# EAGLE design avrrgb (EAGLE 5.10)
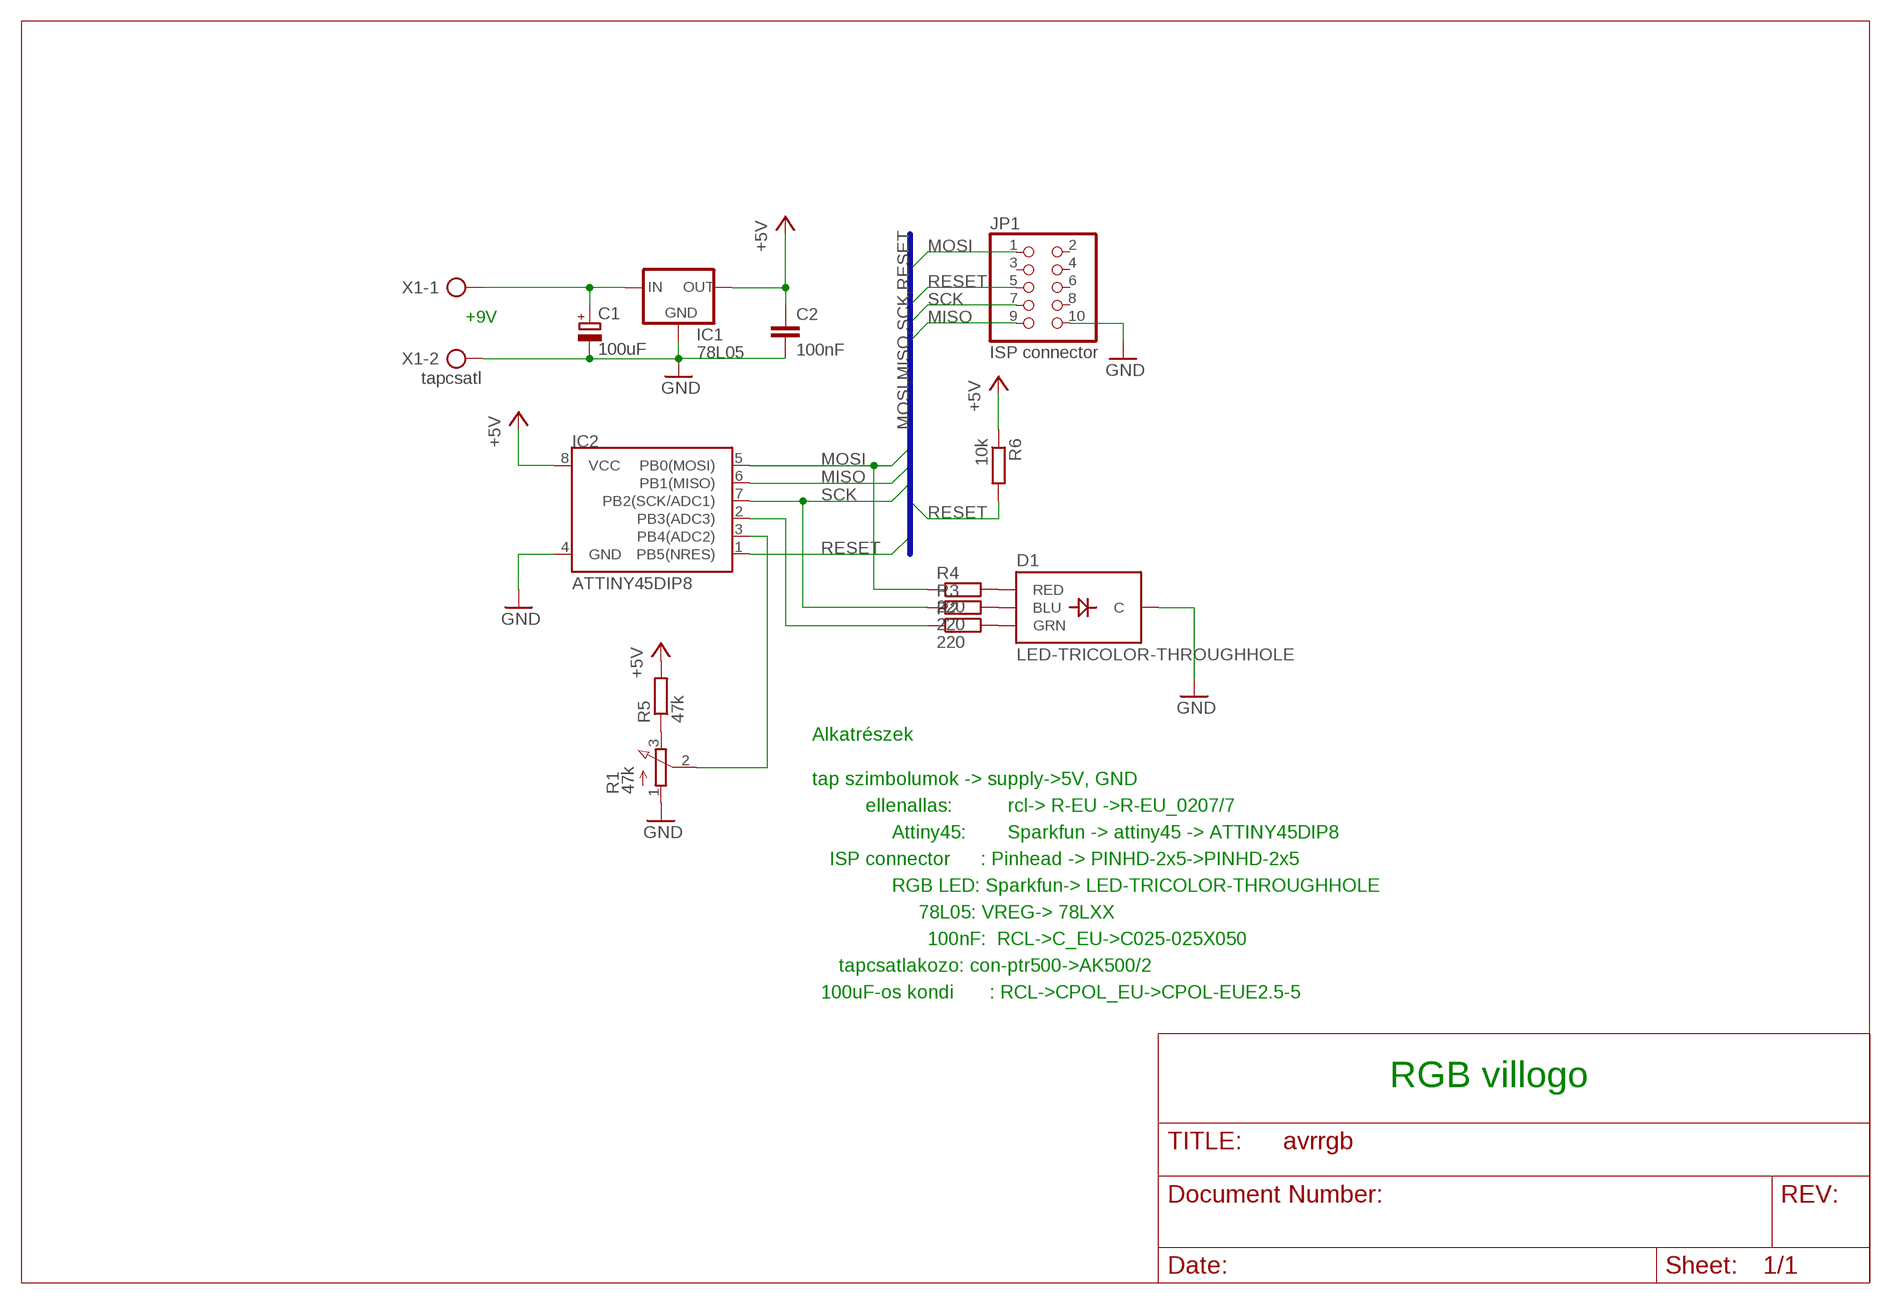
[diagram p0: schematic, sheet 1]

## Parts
C1  100uF  CPOL-EUE2.5-5  [E2,5-5]
C2  100nF  C-EU025-025X050  [C025-025X050]
D1  LED-TRICOLOR-THROUGHHOLE  [LED-TRICOLOR-THROUGHHOLE]
IC1  78L05  78LXX  [78LXX]
IC2  ATTINY45DIP8  [DIP08]
JP1  ISP connector  PINHD-2X5  [2X05]
R1  47k  3RP/1610N  [3RP/1610N]
R2  220  R-EU_0207/7  [0207/7]
R3  220  R-EU_0207/7  [0207/7]
R4  220  R-EU_0207/7  [0207/7]
R5  47k  R-EU_0207/7  [0207/7]
R6  10k  R-EU_0207/7  [0207/7]
X1  tapcsatl  AK500/2  [AK500/2]

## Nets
+5V: C2.1 IC1.OUT IC2.8(VCC) R5.2 R6.1
GND: C1.- C2.2 D1.GND(C) IC1.GND IC2.4(GND) JP1.10 R1.1(A) X1.2
MISO: IC2.6(PB1(MISO)) JP1.9
MOSI: IC2.5(PB0(MOSI)) JP1.1 R4.1
N$1: C1.+ IC1.IN X1.1
N$2: D1.GRN R2.2
N$3: D1.BLU R3.2
N$4: D1.RED R4.2
N$5: R1.3(E) R5.1
N$6: IC2.3(PB4(ADC2)) R1.2(S)
N$7: IC2.2(PB3(ADC3)) R2.1
RESET: IC2.1(PB5(NRES)) JP1.5 R6.2
SCK: IC2.7(PB2(SCK/ADC1)) JP1.7 R3.1
Unconnected: JP1.2 JP1.3 JP1.4 JP1.6 JP1.8

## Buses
MOSI,MISO,SCK,RESET

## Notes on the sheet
- +9V
- Alkatrészek
- tap szimbolumok -> supply->5V, GND
- ellenallas: | rcl-> R-EU ->R-EU_0207/7
- Attiny45: | Sparkfun -> attiny45 -> ATTINY45DIP8
- ISP connector | : Pinhead -> PINHD-2x5->PINHD-2x5
- RGB LED: Sparkfun-> LED-TRICOLOR-THROUGHHOLE
- 78L05: VREG-> 78LXX
- 100nF:  RCL->C_EU->C025-025X050
- tapcsatlakozo: con-ptr500->AK500/2
- 100uF-os kondi | : RCL->CPOL_EU->CPOL-EUE2.5-5
- RGB villogo

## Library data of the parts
C1 = rcl:CPOL-EU: POLARIZED CAPACITOR, European symbol
C2 = rcl:C-EU: CAPACITOR, European symbol
D1 = SparkFun:LED-TRICOLOR-THROUGHHOLE
IC1 = v-reg:78LXX: VOLTAGE REGULATOR
IC2 = SparkFun:ATTINY45: Atmel ATTiny45
JP1 = pinhead:PINHD-2X5: PIN HEADER
R1 = pot:3RP/1610N: 16mm Potentiometer one level Source: http://www.alphapotentiometers.net/html/16mm_pot_2.html
R2-R6 = rcl:R-EU_: RESISTOR, European symbol
X1 = con-ptr500:AK500/2: CONNECTOR

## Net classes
0 default: clearance 0.762 mm

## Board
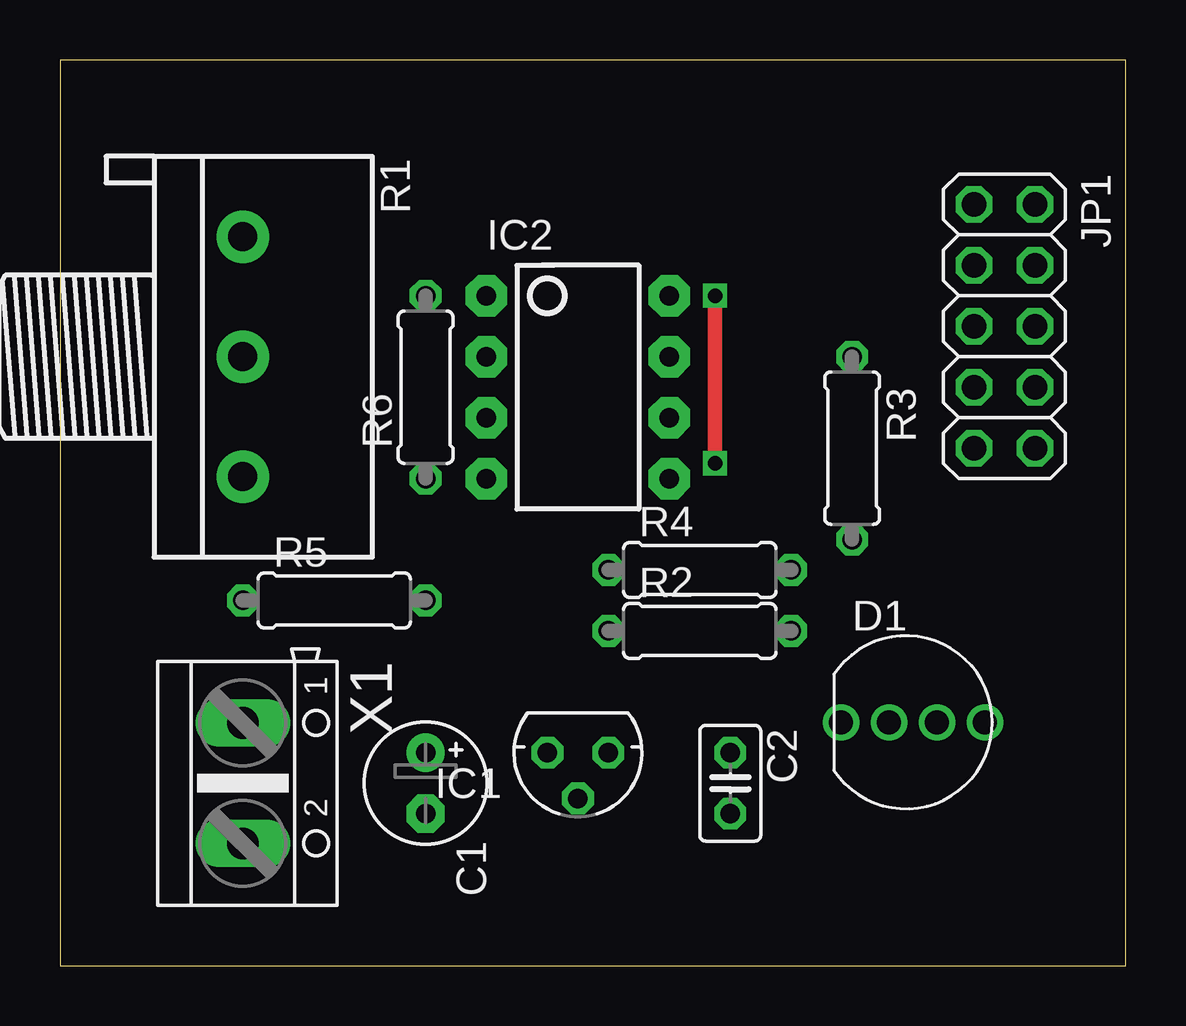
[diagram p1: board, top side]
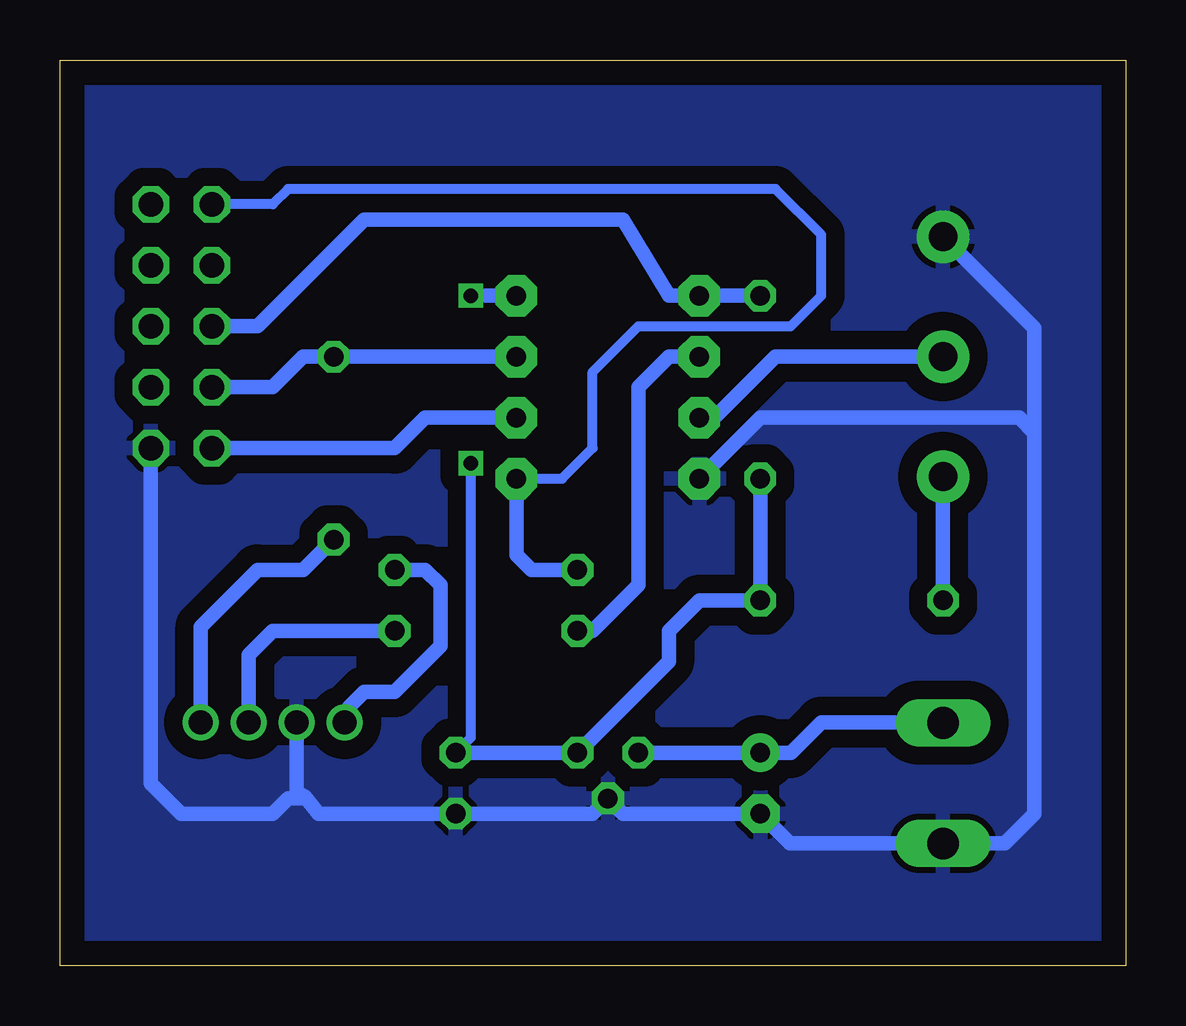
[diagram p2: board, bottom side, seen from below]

Size 44.43 x 37.77 mm. Coordinates in mm from the lower left corner, seen from the top.
Outline: 0,0 44.43,0 44.43,37.77 0,37.77 0,0
Copper layers (1*16): Top 0.035mm / dielectric 1.5mm / Bottom 0.035mm
Design rules "default": minimum track width 10mil, minimum drill 24mil, track to track 8mil, track to pad 8mil, pad to pad 8mil, via to via 8mil, smd to smd 8mil, copper to edge 40mil, drill to drill 8mil, minimum pad ring 10mil, minimum via ring 8mil, stop-mask expansion 4mil, vias tented up to drill 0mil, thermal gap 10mil

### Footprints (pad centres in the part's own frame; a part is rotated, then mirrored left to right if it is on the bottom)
E2,5-5 = drill 0.813 pad 1.6 round: + -1.27,0 | drill 0.813 pad 1.6 octagon: - 1.27,0
C025-025X050 = drill 0.813 octagon: 1 -1.27,0; 2 1.27,0
LED-TRICOLOR-THROUGHHOLE = drill 1 round: BLU 3,0; GND -1,0; GRN 1,0; RED -3,0
78LXX = drill 0.813 octagon: GND 0,1.905; IN 1.27,0; OUT -1.27,0
DIP08 = drill 0.813 pad 1.727 octagon: 1 -3.81,-3.81; 2 -1.27,-3.81; 3 1.27,-3.81; 4 3.81,-3.81; 5 3.81,3.81; 6 1.27,3.81; 7 -1.27,3.81; 8 -3.81,3.81
2X05 = drill 1.016 octagon: 1 -5.08,-1.27; 2 -5.08,1.27; 3 -2.54,-1.27; 4 -2.54,1.27; 5 0,-1.27; 6 0,1.27; 7 2.54,-1.27; 8 2.54,1.27; 9 5.08,-1.27; 10 5.08,1.27
3RP/1610N = drill 1.2 pad 2.184 round: 1 -5,0; 2 0,0; 3 5,0
0207/7 = drill 0.813 octagon: 1 -3.81,0; 2 3.81,0
AK500/2 = drill 1.321 long: 1 -2.515,0; 2 2.515,0

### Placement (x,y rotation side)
C1  15.24,7.62 270 top
C2  27.94,7.62 270 top
D1  35.56,10.16 0 top
IC1  21.59,8.89 180 top
IC2  21.59,24.13 270 top
JP1  39.37,26.67 270 top
R1  7.62,25.4 270 top
R2  26.67,13.97 0 top
R3  33.02,21.59 270 top
R4  26.67,16.51 0 top
R5  11.43,15.24 0 top
R6  15.24,24.13 90 top
X1  7.62,7.62 270 top

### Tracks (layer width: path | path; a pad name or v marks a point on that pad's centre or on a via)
+5V  (via drill 0.6)
  Top 0.61: v27.3,20.95 v27.3,27.94
  Bottom 0.406: v27.3,20.95 27.3,9.53 C2.1
  Bottom 0.61: R6.1 R5.2 17.78,15.24 19.05,13.97 19.05,12.7 IC1.OUT C2.1 | v27.3,27.94 IC2.8
GND
  Bottom 0.61: R1.1 3.81,26.59 3.81,22.23 | 3.81,22.23 3.81,6.35 5.05,5.11 X1.2 14,5.11 C1.- 20.95,6.35 IC1.GND 22.22,6.35 C2.2 33.66,6.35 34.24,7.07 | D1.GND 34.56,7.25 34.24,7.07 | JP1.10 40.64,7.62 39.37,6.35 35.56,6.35 34.92,6.99 34.32,6.99 34.24,7.07 | IC2.4 15.24,22.86 4.45,22.86 3.81,22.23
  pour Bottom: -2.54,39.37 46.35,39.37 46.35,-3.81 -3.18,-3.81 -3.18,38.1
MISO
  Bottom 0.61: JP1.9 30.48,21.59 29.21,22.86 IC2.6
MOSI
  Bottom 0.406: IC2.5 23.49,20.32 22.22,21.59 22.22,24.77 20.32,26.67 13.97,26.67 12.7,27.94 12.7,30.48 14.61,32.38 34.92,32.38 35.56,31.75 JP1.1
  Bottom 0.61: R4.1 24.77,16.51 25.4,17.14 IC2.5
N$1
  Bottom 0.61: IC1.IN C1.+ 13.97,8.89 12.7,10.16 7.62,10.16 X1.1
N$2
  Bottom 0.61: D1.GRN 36.56,12.97 35.56,13.97 R2.2
N$3
  Bottom 0.61: D1.BLU 38.56,14.14 36.2,16.51 34.29,16.51 R3.2
N$4
  Bottom 0.61: R4.2 29.21,16.51 28.58,15.88 28.58,13.34 30.48,11.43 31.75,11.43 32.38,10.79 32.38,10.34 D1.RED
N$5
  Bottom 0.61: R5.1 R1.3
N$6
  Bottom 0.61: R1.2 14.61,25.4 17.14,22.86 IC2.3
N$7
  Bottom 0.61: R2.1 22.22,13.97 20.32,15.88 20.32,24.13 19.05,25.4 IC2.2
RESET
  Bottom 0.61: R6.2 IC2.1 19.05,27.94 20.95,31.11 31.75,31.11 36.2,26.67 JP1.5
SCK
  Bottom 0.61: JP1.7 35.56,24.13 34.29,25.4 R3.1 IC2.7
